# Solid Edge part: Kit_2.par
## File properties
Author: bmolnar
Last saved by: ahadarics
Revision: 77
Sűrűség: 0,000 kg/m^3
Pontosság: 0,990
Username: bmolnar
Dokumentum tartalom típus: 0
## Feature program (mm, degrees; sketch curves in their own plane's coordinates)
base feature "unnamed BaseFeature 1"
sketch for "unnamed Hole 1" plane through (-28.25, 28.25, 5) normal (0, 0, -1) x-axis (0, -1, 0)
  hole centre (0, 0) bore radius 3.3235
hole "unnamed Hole 1" through
sketch for "unnamed Hole 2" plane through (-28.25, 28.25, 5) normal (0, 0, -1) x-axis (0, -1, 0)
  hole centre (56.5, 0) bore radius 3.3235
hole "unnamed Hole 2" through
sketch for "unnamed Hole 3" plane through (-28.25, 28.25, 5) normal (0, 0, -1) x-axis (0, -1, 0)
  hole centre (0, -56.5) bore radius 3.3235
hole "unnamed Hole 3" through
sketch for "unnamed Hole 4" plane through (-28.25, 28.25, 5) normal (0, 0, -1) x-axis (0, -1, 0)
  hole centre (56.5, -56.5) bore radius 3.3235
hole "unnamed Hole 4" through
pattern "unnamed Pattern 1" of "unnamed Hole 1", "unnamed Hole 2", "unnamed Hole 3", "unnamed Hole 4"
thread "unnamed Thread 1"
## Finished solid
Body 1: solid body, 295 faces, 736 edges, 457 vertices.
  Faces by surface: plane 140, cylinder 74, swept 61, cone 11, torus 8, spline 1
  Edges by curve: line 431, circle 139, spline 126, ellipse 30, curve on surface 9, intersection 1
Bounding box of the edges (mm; curved faces can reach further): 77.000 x 77.000 x 13.750, from (-38.5, -38.5, 0) to (38.5, 38.5, 13.75).
Cylindrical faces by radius (mm): R0.2 x48, R0.2008 x2, R0.2009 x2, R0.402 x1, R0.4899 x1, R2 x1, R3.3235 x4, R4.283 x1, R4.9 x4, R5.15 x4, R5.25 x4, R6 x1, R17.0898 x1
Conical faces (half-angle, radius in mm at the cone's reference point): 0.5 deg R12 x4, 0.5 deg R13.5 x2, 45 deg R3.32 x4, 45 deg R6.25 x1
Toroidal faces (ring radius, tube radius in mm): R4.7 r0.2 x8
Planar faces by outward normal: +x 12, +y 14, +z 1, -x 15, -y 13, -z 18, oblique 67
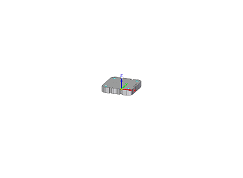
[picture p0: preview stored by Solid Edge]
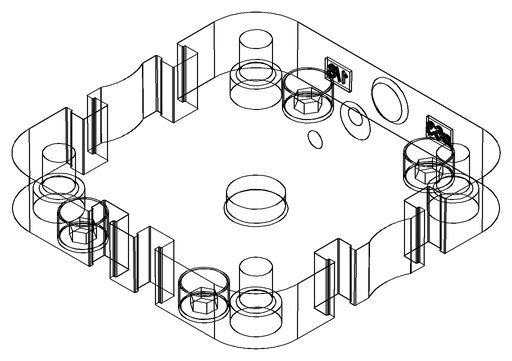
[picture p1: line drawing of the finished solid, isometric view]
